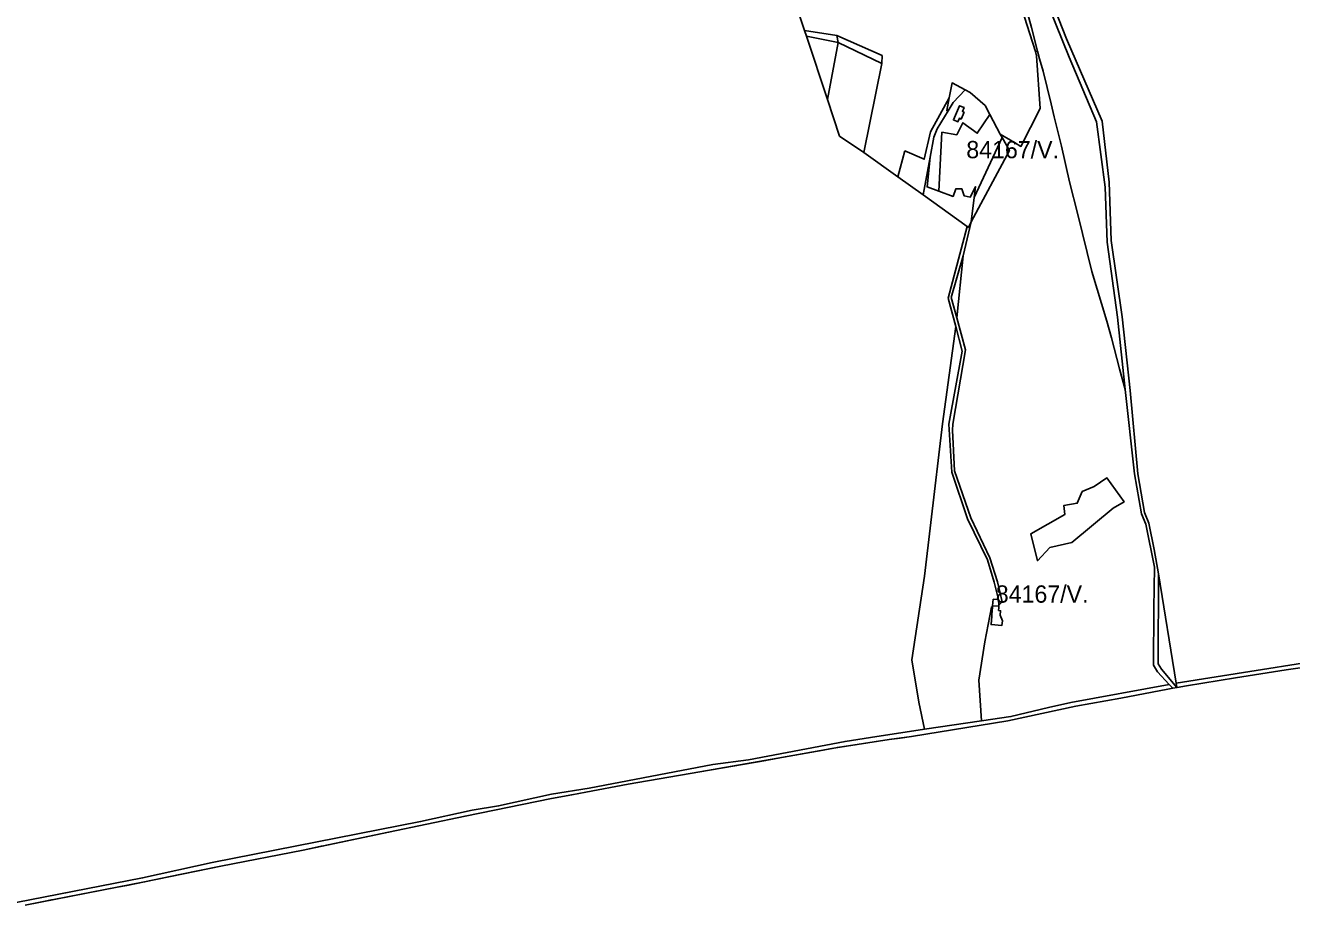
# Model space of a CAD drawing. Extents: x -477304 to -465429, y -1159113 to -1149210.
# Drawn here: x -471254 to -470157, y -1159044 to -1158279 of the extents above; entities that cross this region are included whole.
import ezdxf

# ---------------------------------------------------------------- set-up
doc = ezdxf.new("R2010")
doc.units = 0
for name, color, linetype in [('BPEJ_s', 7, 'Continuous'), ('orna_s', 7, 'Continuous'), ('PUPFL_s', 7, 'Continuous'), ('trav_porost_s', 7, 'Continuous')]:
    doc.layers.add(name, color=color, linetype=linetype)

msp = doc.modelspace()

# ---------------------------------------------------------------- linework, layer by layer
at = {"layer": 'BPEJ_s'}
for points in [[(-470434.93, -1158449.45), (-470437.19, -1158454.22), (-470438.31, -1158453.42), (-470476.36, -1158425.95), (-470470.39, -1158393.2), (-470467.23, -1158375.87), (-470464.41, -1158368.79), (-470454.72, -1158353.08), (-470455.93, -1158352.91), (-470453.94, -1158341.77), (-470451.3, -1158328.99), (-470440.07, -1158335.06), (-470435.79, -1158337.31), (-470422.62, -1158348.64), (-470418.56, -1158356.43), (-470409.8, -1158373.24), (-470408, -1158376.39), (-470401.7, -1158387.41)], [(-470410.79, -1158781.49), (-470410.72, -1158782.4), (-470416.23, -1158781.97), (-470415.74, -1158776.36), (-470411.16, -1158776.66)]]:
    msp.add_lwpolyline(points, close=True, dxfattribs=at)
for points in [[(-470470.39, -1158393.2), (-470467.23, -1158375.87), (-470464.41, -1158368.79), (-470454.72, -1158353.08), (-470455.93, -1158352.91), (-470453.94, -1158341.77), (-470451.3, -1158328.99), (-470440.07, -1158335.06), (-470435.79, -1158337.31), (-470422.62, -1158348.64), (-470418.56, -1158356.43), (-470409.8, -1158373.24), (-470408, -1158376.39), (-470401.7, -1158387.41), (-470434.93, -1158449.45), (-470437.19, -1158454.22), (-470438.31, -1158453.42), (-470476.36, -1158425.95), (-470470.39, -1158393.2)], [(-470415.74, -1158776.36), (-470411.16, -1158776.66), (-470410.79, -1158781.49), (-470410.72, -1158782.4), (-470416.23, -1158781.97), (-470415.74, -1158776.36)], [(-470248.25, -1158851.38), (-470205.81, -1158844.38), (-470162.08, -1158837.62), (-470077.97, -1158825.25)], [(-470264.48, -1158854.28), (-470260.21, -1158853.52), (-470256.51, -1158852.86), (-470248.25, -1158851.38)], [(-470541.01, -1158903.42), (-470505.9, -1158897.99), (-470496.2, -1158896.6), (-470486.5, -1158895.21), (-470403.18, -1158881.79), (-470344.16, -1158869.01), (-470305.09, -1158861.97), (-470264.48, -1158854.28)], [(-471254.45, -1159041.38), (-471240.01, -1159038.58), (-471231.47, -1159036.92), (-471231.41, -1159036.91), (-471229.43, -1159036.53), (-471174.71, -1159025.92), (-471166.37, -1159024.3), (-471150.91, -1159021.3), (-471120.41, -1159015), (-471084.88, -1159007.66), (-471013.36, -1158993.64), (-470997.93, -1158990.44), (-470997.3, -1158990.31), (-470939.44, -1158978.32), (-470873.27, -1158964.2), (-470798.27, -1158949.14), (-470780.79, -1158945.73), (-470768.71, -1158943.55), (-470731.84, -1158936.68), (-470669.83, -1158925.85), (-470612.64, -1158915.98), (-470609.99, -1158915.53), (-470606.75, -1158914.97), (-470602.29, -1158914.2), (-470563.15, -1158907.13), (-470557.12, -1158906.04), (-470552.18, -1158905.15), (-470550.84, -1158904.94), (-470541.01, -1158903.42)]]:
    msp.add_lwpolyline(points, dxfattribs=at)
at = {"layer": 'orna_s'}
msp.add_lwpolyline([(-470418.56, -1158356.43), (-470409.8, -1158373.24), (-470408, -1158376.39), (-470432.17, -1158428.38), (-470430.98, -1158418.87), (-470435.63, -1158427.84), (-470440.98, -1158426.8), (-470443.05, -1158420.68), (-470448.22, -1158420.76), (-470450.56, -1158427.34), (-470462.91, -1158422.82), (-470460.16, -1158371.76), (-470447.33, -1158373.84), (-470441.94, -1158363.45), (-470429.62, -1158372.59)], close=True, dxfattribs=at)
at = {"layer": 'PUPFL_s'}
msp.add_line((-470260.25, -1158853.48), (-470260.24, -1158853.48), dxfattribs=at)
for points in [[(-470078.41, -1158820.73), (-470257.15, -1158848.93), (-470272.61, -1158754.31), (-470276.33, -1158733.34), (-470280.8, -1158710.29), (-470284.69, -1158701.09), (-470290.32, -1158667.6), (-470297.12, -1158595.39), (-470303.98, -1158531.66), (-470313.56, -1158465.47), (-470315.31, -1158415.08), (-470321.2, -1158362.1), (-470352.34, -1158290.86), (-470369.23, -1158247.07), (-470385.09, -1158219.48), (-470398.95, -1158160.87), (-470415.65, -1158111.06), (-470405.49, -1158078.61), (-470403.09, -1158045.71), (-470404.35, -1157991.63), (-470397.36, -1157942.93), (-469953.75, -1157587.77)], [(-470593.85, -1158239.19), (-470579.16, -1158283.52), (-470577.52, -1158288.46), (-470559.3, -1158343.45)], [(-470373.12, -1158249.08), (-470349.94, -1158306.53), (-470326.18, -1158362.68), (-470318.8, -1158419.22), (-470317.05, -1158467.09), (-470307.93, -1158531.85), (-470301.56, -1158594.68), (-470306.29, -1158576.62), (-470313.33, -1158549.92), (-470317.16, -1158535.27), (-470330.34, -1158492.27), (-470342.29, -1158443.11), (-470349.72, -1158414.63), (-470356.64, -1158383.8), (-470362.84, -1158358.29), (-470365.38, -1158347.13), (-470372.59, -1158318.65), (-470375.68, -1158308.07), (-470377.36, -1158301.37), (-470382.52, -1158280.8), (-470389.18, -1158256.77)], [(-470559.3, -1158343.45), (-470548.86, -1158374.97), (-470527.81, -1158389.22), (-470498.26, -1158410.32), (-470476.36, -1158425.95), (-470438.31, -1158453.42), (-470454.85, -1158515.42), (-470447.98, -1158540.1), (-470459.69, -1158624.4), (-470469.76, -1158709.89), (-470475.22, -1158756.26), (-470486.3, -1158828.8), (-470480.06, -1158865.44), (-470475.17, -1158888.79)], [(-470260.24, -1158853.48), (-470263.38, -1158850.11), (-470348.39, -1158865.85), (-470367.72, -1158870.18), (-470400.38, -1158877.99), (-470425.96, -1158881.82), (-470475.17, -1158888.79), (-470522.12, -1158896.12), (-470544.03, -1158899.54), (-470627.64, -1158915.36), (-470658.51, -1158919.5), (-470765.66, -1158940.03), (-470798.27, -1158945.34), (-470844.24, -1158955.48), (-470867.06, -1158959.06), (-470911.78, -1158968.97), (-471092.36, -1159004.59), (-471152.65, -1159017.86), (-471286.02, -1159043.61)], [(-471254.45, -1159041.38), (-471174.71, -1159025.92), (-471150.91, -1159021.3), (-471084.88, -1159007.66), (-471013.36, -1158993.64), (-470939.44, -1158978.32), (-470873.27, -1158964.2), (-470798.27, -1158949.14), (-470780.79, -1158945.73), (-470768.71, -1158943.55), (-470731.84, -1158936.68), (-470669.83, -1158925.85), (-470602.29, -1158914.2), (-470552.18, -1158905.15), (-470505.9, -1158897.99), (-470486.5, -1158895.21), (-470403.18, -1158881.79), (-470344.16, -1158869.01), (-470305.09, -1158861.97), (-470264.48, -1158854.28)], [(-470264.48, -1158854.28), (-470260.21, -1158853.52), (-470260.25, -1158853.48)], [(-470475.17, -1158888.79), (-470522.12, -1158896.12), (-470544.03, -1158899.54), (-470627.64, -1158915.36), (-470658.51, -1158919.5), (-470765.66, -1158940.03), (-470798.27, -1158945.34), (-470844.24, -1158955.48), (-470867.06, -1158959.06), (-470911.78, -1158968.97), (-471092.36, -1159004.59), (-471152.65, -1159017.86), (-471286.02, -1159043.61)]]:
    msp.add_lwpolyline(points, dxfattribs=at)
for points in [[(-470414.2, -1158221.23), (-470430.5, -1158218.59), (-470466.8, -1158212.72), (-470460.61, -1158089.39), (-470438.26, -1158093.62), (-470430.06, -1158097.97), (-470419.29, -1158140.76), (-470403.7, -1158200.12), (-470398.18, -1158221.77), (-470389.18, -1158256.77), (-470382.52, -1158280.8), (-470377.36, -1158301.37), (-470379.16, -1158301.69), (-470391.35, -1158263.82), (-470402.58, -1158223.11)], [(-470577.52, -1158288.46), (-470579.16, -1158283.52), (-470551.32, -1158287.81), (-470550.05, -1158293.84)], [(-470577.52, -1158288.46), (-470550.05, -1158293.84), (-470559.3, -1158343.45)], [(-470511.87, -1158305.3), (-470512.15, -1158312.01), (-470550.05, -1158293.84), (-470551.32, -1158287.81)], [(-470559.3, -1158343.45), (-470550.05, -1158293.84), (-470512.15, -1158312.01), (-470527.81, -1158389.22), (-470548.86, -1158374.97)], [(-470411.02, -1158786.23), (-470410.82, -1158783.74), (-470410.72, -1158782.4), (-470410.79, -1158781.49), (-470408, -1158778.62), (-470411.93, -1158761.35), (-470418.55, -1158740.55), (-470435.17, -1158705.86), (-470449.16, -1158664.98), (-470451.04, -1158629.73), (-470450.8, -1158624.66), (-470439.59, -1158560.3), (-470447.21, -1158532.44), (-470441.83, -1158478.88), (-470434.93, -1158449.45), (-470401.7, -1158387.41), (-470408, -1158376.39), (-470409.8, -1158373.24), (-470397.38, -1158380.61), (-470391.76, -1158383.94), (-470374.92, -1158351.1), (-470378.11, -1158305.42), (-470379.16, -1158301.69), (-470377.36, -1158301.37), (-470375.68, -1158308.07), (-470372.59, -1158318.65), (-470365.38, -1158347.13), (-470362.84, -1158358.29), (-470356.64, -1158383.8), (-470349.72, -1158414.63), (-470342.29, -1158443.11), (-470330.34, -1158492.27), (-470317.16, -1158535.27), (-470313.33, -1158549.92), (-470306.29, -1158576.62), (-470301.56, -1158594.68), (-470293.43, -1158667.61), (-470287.32, -1158702.26), (-470283.41, -1158711.17), (-470276.13, -1158748.53), (-470276.49, -1158784.26), (-470276.98, -1158833.54), (-470273.47, -1158839.21), (-470263.38, -1158850.11), (-470348.39, -1158865.85), (-470367.72, -1158870.18), (-470400.38, -1158877.99), (-470425.96, -1158881.82), (-470428.08, -1158846.41), (-470423.1, -1158813.29), (-470417.31, -1158783.19), (-470416.33, -1158783.25), (-470416.83, -1158789.65), (-470416.96, -1158791.33), (-470417.2, -1158794.38), (-470417.51, -1158798.31), (-470408.12, -1158799.06), (-470407.81, -1158795.12), (-470409.6, -1158790.22), (-470409.3, -1158786.36)], [(-470492.23, -1158387.7), (-470475.51, -1158395.15), (-470469.96, -1158371.44), (-470453.94, -1158341.77), (-470455.93, -1158352.91), (-470454.72, -1158353.08), (-470464.41, -1158368.79), (-470467.23, -1158375.87), (-470470.39, -1158393.2), (-470476.36, -1158425.95), (-470498.26, -1158410.32)], [(-470447.21, -1158532.44), (-470452.01, -1158514.89), (-470441.83, -1158478.88)], [(-470442.55, -1158561.38), (-470454.17, -1158624.79), (-470451.45, -1158666.36), (-470438.13, -1158706.64), (-470420.8, -1158742.21), (-470414.94, -1158761.43), (-470411.16, -1158776.66), (-470415.74, -1158776.36), (-470416.23, -1158781.97), (-470416.33, -1158783.25), (-470417.31, -1158783.19), (-470423.1, -1158813.29), (-470428.08, -1158846.41), (-470425.96, -1158881.82), (-470475.17, -1158888.79), (-470480.06, -1158865.44), (-470486.3, -1158828.8), (-470475.22, -1158756.26), (-470469.76, -1158709.89), (-470459.69, -1158624.4), (-470447.98, -1158540.1)], [(-470338.56, -1158683.11), (-470342.88, -1158693.2), (-470354.56, -1158695.24), (-470353.73, -1158703.06), (-470383.03, -1158719.6), (-470377.5, -1158742.99), (-470366.62, -1158731.63), (-470347.53, -1158727.07), (-470311.75, -1158697.43), (-470302.38, -1158692.05), (-470317.28, -1158671.17), (-470328.13, -1158678.67)], [(-470383.03, -1158719.6), (-470353.73, -1158703.06), (-470354.56, -1158695.24), (-470342.88, -1158693.2), (-470338.56, -1158683.11), (-470328.13, -1158678.67), (-470317.28, -1158671.17), (-470302.38, -1158692.05), (-470311.75, -1158697.43), (-470347.53, -1158727.07), (-470366.62, -1158731.63), (-470377.5, -1158742.99)], [(-470256.52, -1158852.78), (-470269.88, -1158837.05), (-470272.93, -1158832.35), (-470272.61, -1158754.31), (-470257.15, -1158848.93)]]:
    msp.add_lwpolyline(points, close=True, dxfattribs=at)
at = {"layer": 'trav_porost_s'}
for points in [[(-470470.39, -1158393.2), (-470467.23, -1158375.87), (-470464.41, -1158368.79), (-470454.72, -1158353.08), (-470450.35, -1158346), (-470440.07, -1158335.06), (-470435.79, -1158337.31), (-470422.62, -1158348.64), (-470418.56, -1158356.43), (-470429.62, -1158372.59), (-470441.94, -1158363.45), (-470447.33, -1158373.84), (-470460.16, -1158371.76), (-470462.91, -1158422.82), (-470473.03, -1158419.12)], [(-470453.94, -1158341.77), (-470451.3, -1158328.99), (-470440.07, -1158335.06), (-470450.35, -1158346), (-470454.72, -1158353.08), (-470455.93, -1158352.91)], [(-470440.93, -1158354.26), (-470442.45, -1158353.6), (-470441.02, -1158350.31), (-470444.79, -1158348.69), (-470450.13, -1158361.05), (-470446.37, -1158362.68), (-470445.03, -1158359.58), (-470443.51, -1158360.23)], [(-470434.93, -1158449.45), (-470432.17, -1158428.38), (-470408, -1158376.39), (-470401.7, -1158387.41)], [(-470450.56, -1158427.34), (-470448.22, -1158420.76), (-470443.05, -1158420.68), (-470440.98, -1158426.8), (-470435.63, -1158427.84), (-470430.98, -1158418.87), (-470432.17, -1158428.38), (-470434.93, -1158449.45), (-470437.19, -1158454.22), (-470438.31, -1158453.42), (-470476.36, -1158425.95), (-470470.39, -1158393.2), (-470473.03, -1158419.12), (-470462.91, -1158422.82)], [(-470410.72, -1158782.4), (-470416.23, -1158781.97), (-470415.74, -1158776.36), (-470411.16, -1158776.66), (-470410.79, -1158781.49)]]:
    msp.add_lwpolyline(points, close=True, dxfattribs=at)

# ---------------------------------------------------------------- texts
at = {"layer": 'BPEJ_s'}
for p in [(-470439.03, -1158394.25), (-470413.48, -1158779.35)]:
    msp.add_text('84167/V.', height=15, dxfattribs=at).set_placement(p)

doc.saveas('drawing.dxf')
